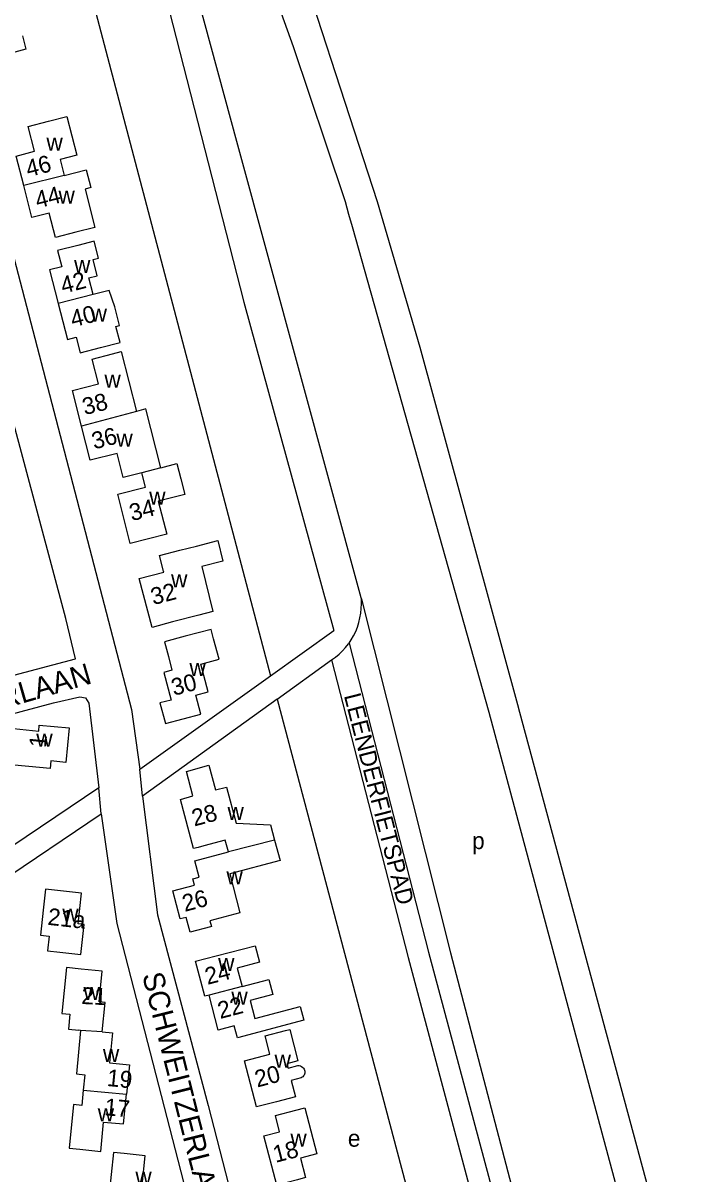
# Model space of a CAD drawing. Extents: x 161093 to 163177, y 379000 to 380904.
# Drawn here: x 162658.3 to 162814.2, y 380357.5 to 380629.6 of the extents above; entities that cross this region are included whole.
import ezdxf

# ---------------------------------------------------------------- set-up
doc = ezdxf.new("R2010")
doc.units = 0
for name, color, linetype in [('BLT_Basislijn', 7, 'Continuous'), ('BLT_Bebouwing', 7, 'Continuous'), ('BLT_Centroide', 7, 'Continuous'), ('BLT_Huisnummer', 7, 'Continuous'), ('BLT_Onderverdeling_panden', 7, 'Continuous'), ('BLT_Straatnaam', 7, 'Continuous'), ('BLT_Straatnaam_verkleind', 7, 'Continuous')]:
    doc.layers.add(name, color=color, linetype=linetype)

msp = doc.modelspace()

# ---------------------------------------------------------------- linework, layer by layer
at = {"layer": 'BLT_Basislijn'}
for p, q in [((162682.53, 380698.36), (162708.97, 380600.8)), ((162726.63, 380634.35), (162741.91, 380587.43)), ((162708.97, 380600.8), (162738.11, 380493.77)), ((162735.18, 380584.45), (162736.02, 380581.49)), ((162710.43, 380563.6), (162731.72, 380485.97)), ((162738.11, 380493.77), (162738.2, 380493.41)), ((162738.2, 380493.41), (162759.26, 380409.76)), ((162716.76, 380475.26), (162731.72, 380485.97)), ((162735.29, 380483.01), (162754.08, 380409.94)), ((162718.35, 380469.79), (162731.15, 380479.02)), ((162731.15, 380479.02), (162749.24, 380408.7)), ((162685.9, 380453.19), (162716.76, 380475.26)), ((162718.35, 380469.79), (162686.52, 380446.86)), ((162768.34, 380466.65), (162806.16, 380325.66)), ((162775.08, 380468.52), (162775.56, 380466.65)), ((162775.56, 380466.65), (162814.19, 380323.58)), ((162686.52, 380446.86), (162685.9, 380453.19)), ((162676.14, 380448.82), (162638.7, 380423.5)), ((162676.76, 380442.66), (162676.14, 380448.82)), ((162647.54, 380422.95), (162676.76, 380442.66)), ((162754.08, 380409.94), (162773.23, 380338.47)), ((162759.26, 380409.76), (162777.73, 380339.31)), ((162749.24, 380408.7), (162768.4, 380337.17))]:
    msp.add_line(p, q, dxfattribs=at)
for points in [[(162521.72, 380713.91), (162569.39, 380726.78), (162570.66, 380726.33), (162600, 380707.66), (162646.36, 380678.17), (162666.62, 380665.58), (162716.76, 380475.26)], [(162674.84, 380697.09), (162690.28, 380642.46), (162710.43, 380563.6)], [(162704.48, 380673.18), (162722.08, 380624.03), (162729.85, 380601.06)], [(162635.73, 380632.52), (162634.81, 380628.02), (162628.89, 380606.34), (162635.55, 380602.41), (162638.7, 380600.16), (162645.01, 380593.94), (162646.61, 380592.03), (162652.23, 380583.53), (162655.59, 380576), (162683.93, 380467.29), (162685.9, 380453.19)], [(162729.85, 380601.06), (162734.4, 380587.43), (162735.18, 380584.45)], [(162741.91, 380587.43), (162752.02, 380552.96), (162775.08, 380468.52)], [(162736.02, 380581.49), (162768.34, 380466.65)], [(162611.52, 380463.97), (162612.48, 380463.94), (162614.96, 380464.57), (162670.7, 380479.32), (162668.42, 380488.85), (162655.43, 380537.18), (162622.45, 380529.94), (162611.45, 380529.55), (162606.04, 380530.03), (162600, 380531.3), (162592.93, 380532.79), (162582.27, 380535.94), (162507.49, 380559.04), (162504.08, 380561.39)], [(162735.29, 380483.01), (162735.81, 380483.78), (162736.37, 380484.75), (162736.86, 380485.76), (162737.28, 380486.79), (162737.62, 380487.86), (162737.88, 380488.95), (162738.07, 380490.05), (162738.18, 380491.16), (162738.2, 380492.28), (162738.2, 380493.41)], [(162731.15, 380479.02), (162732.07, 380479.67), (162732.93, 380480.38), (162733.74, 380481.15), (162734.49, 380481.98), (162735.18, 380482.85), (162735.29, 380483.01)], [(162609.26, 380454.6), (162617.51, 380456.01), (162665.48, 380468.91), (162671.67, 380470.27), (162673.04, 380470.08), (162673.82, 380468.82), (162676.14, 380448.82)], [(162718.35, 380469.79), (162769.85, 380275.36), (162777.91, 380251.24), (162777.23, 380250.72), (162770.85, 380248.18), (162757.24, 380224.32)], [(162686.52, 380446.86), (162690.06, 380418.81), (162702.03, 380373.69), (162725.23, 380283.43), (162725.87, 380280.88), (162726.14, 380277.12), (162726.26, 380268.1), (162725.19, 380258.43), (162721.09, 380245.82), (162714.65, 380234.57), (162708.48, 380227.38), (162705.29, 380224.32)], [(162676.76, 380442.66), (162680.45, 380416.71), (162702.12, 380332.61), (162714.84, 380284.51), (162715.91, 380269.96), (162715.24, 380261.62), (162713.44, 380253.95), (162710.56, 380247.24), (162703.72, 380236.16), (162696.64, 380228.93), (162690.51, 380224.32)]]:
    msp.add_lwpolyline(points, dxfattribs=at)
at = {"layer": 'BLT_Bebouwing'}
msp.add_line((162671.88, 380391.39), (162671.48, 380391.49), dxfattribs=at)
for points in [[(162658.12, 380626.56), (162658.95, 380623.42), (162652.48, 380621.7), (162653.48, 380617.93), (162652.31, 380617.62), (162654.32, 380610.02)], [(162658.42, 380591.15), (162656.63, 380598.16), (162660.96, 380599.27), (162659.46, 380605.17), (162664.28, 380606.4), (162668.62, 380607.5), (162670.95, 380598.38), (162667.02, 380597.37), (162667.98, 380593.59)], [(162667.98, 380593.59), (162673.21, 380594.92), (162674.29, 380590.71), (162672.92, 380590.36), (162675.23, 380581.28), (162670.76, 380580.14), (162665.91, 380578.91), (162664.45, 380584.63), (162660.35, 380583.59), (162658.42, 380591.15)], [(162674.83, 380565.42), (162673.83, 380569.35), (162675.8, 380569.85), (162674.82, 380573.71), (162676.13, 380574.04), (162675.11, 380578.01), (162671.25, 380577.02), (162666.43, 380575.79), (162667.4, 380571.97), (162664.54, 380571.24), (162666.56, 380563.31)], [(162666.56, 380563.31), (162668.74, 380554.79), (162670.83, 380555.32), (162671.77, 380551.63), (162676.61, 380552.87), (162681.21, 380554.04), (162680.23, 380557.88), (162681.07, 380558.09), (162679.95, 380562.49), (162678.64, 380566.39), (162674.83, 380565.42)], [(162672.11, 380534.28), (162669.95, 380542.74), (162676.08, 380544.31), (162674.59, 380550.16), (162679.43, 380551.4), (162681.43, 380551.91), (162685.04, 380537.77)], [(162690.85, 380524.47), (162687.29, 380538.39), (162685.04, 380537.77)], [(162686.31, 380523.27), (162681.95, 380522.15), (162680.5, 380527.85), (162674.16, 380526.23), (162672.11, 380534.28)], [(162690.85, 380524.47), (162694.62, 380525.43), (162695.54, 380521.82), (162696.47, 380518.15), (162693.35, 380517.35), (162690.22, 380516.55), (162692.21, 380508.77), (162683.6, 380506.57), (162680.63, 380518.19), (162687.17, 380519.86), (162686.31, 380523.27)], [(162695.35, 380504.96), (162699.25, 380505.96), (162704.26, 380507.24), (162705.5, 380502.39), (162700.49, 380501.11), (162703.11, 380490.52), (162699.84, 380489.64), (162693.62, 380488), (162688.78, 380486.73), (162685.74, 380498.29), (162691.5, 380499.81), (162691.46, 380500), (162690.51, 380503.73), (162695.35, 380504.96)], [(162701.99, 380471.51), (162700.27, 380478.05), (162704.58, 380479.18), (162703.3, 380484.02), (162702.71, 380486.24), (162696.55, 380484.62), (162691.68, 380483.34), (162692.61, 380479.83), (162693.46, 380476.61), (162691.5, 380476.09), (162693.23, 380469.53), (162690.62, 380468.85), (162691.89, 380464.02), (162700.27, 380466.23), (162699.08, 380470.74), (162701.99, 380471.51)], [(162654.55, 380462.94), (162661.98, 380462.22), (162662.11, 380463.63), (162669.14, 380462.95), (162668.35, 380454.81), (162664.85, 380455.15), (162664.68, 380453.35), (162653.72, 380454.41), (162654.55, 380462.94)], [(162706.79, 380433.67), (162706.06, 380436.44), (162700.96, 380435.07), (162699.66, 380434.72), (162698.58, 380434.43), (162695.46, 380446.07), (162698.42, 380446.87), (162696.86, 380452.69), (162702.18, 380454.12), (162703.74, 380448.3), (162706.32, 380448.99)], [(162706.32, 380448.99), (162708.62, 380440.41), (162716.75, 380440.07), (162717.71, 380436.46)], [(162717.71, 380436.46), (162719, 380431.59), (162707.09, 380428.43)], [(162707.09, 380428.43), (162709.52, 380419.24), (162702.44, 380417.36), (162702.8, 380415.98), (162702.6, 380415.93), (162697.77, 380414.65), (162696.83, 380418.18), (162695.41, 380417.81), (162693.65, 380424.44), (162698.75, 380425.79), (162698.35, 380427.28), (162699.91, 380427.69), (162698.88, 380431.57), (162706.79, 380433.67)], [(162666.99, 380409.97), (162671.96, 380409.42), (162672.73, 380416.46), (162671.26, 380416.62), (162672.07, 380423.93), (162663.6, 380424.87), (162663.05, 380419.87), (162662.4, 380413.99), (162664.43, 380413.76), (162664.05, 380410.29), (162666.99, 380409.97)], [(162702.21, 380399.79), (162701.2, 380399.52), (162699.04, 380407.8), (162703.88, 380409.06), (162713.13, 380411.47), (162714.15, 380407.55), (162708.9, 380406.18), (162710.04, 380401.82)], [(162676.96, 380391.13), (162677.65, 380398.05), (162676.27, 380398.18), (162676.99, 380405.47), (162672.02, 380405.96), (162668.53, 380406.31), (162667.45, 380395.47), (162669.36, 380395.28), (162669.01, 380391.74), (162671.48, 380391.49)], [(162710.04, 380401.82), (162716.35, 380403.47), (162717.27, 380399.91), (162711.92, 380398.52), (162713.03, 380394.26), (162723.75, 380397.09), (162724.61, 380393.86), (162708.92, 380389.69), (162708.18, 380392.54), (162704.35, 380391.54), (162702.21, 380399.79)], [(162671.88, 380391.39), (162670.87, 380381.18), (162672.86, 380380.98), (162672.5, 380377.35)], [(162676.96, 380391.13), (162679.44, 380390.88), (162678.73, 380383.75), (162683.4, 380383.29), (162682.71, 380376.34)], [(162720.28, 380391.41), (162721.28, 380391.67), (162723.21, 380384.25), (162720.62, 380383.58), (162720.89, 380382.56), (162723.18, 380383.16), (162723.54, 380383.14), (162723.84, 380383.04), (162724.09, 380382.93), (162724.36, 380382.71), (162724.55, 380382.49), (162724.68, 380382.27), (162724.76, 380382.03), (162724.83, 380381.82), (162724.84, 380381.6), (162724.81, 380381.34), (162724.77, 380381.14), (162724.67, 380380.88), (162724.55, 380380.7), (162724.39, 380380.5), (162724.25, 380380.37), (162724.02, 380380.23), (162721.65, 380379.61), (162722.66, 380375.76), (162718.19, 380374.6), (162713.4, 380373.35), (162710.56, 380384.26), (162716.57, 380385.82), (162715.44, 380390.15), (162720.28, 380391.41)], [(162672.5, 380377.35), (162672.14, 380373.71), (162670.16, 380373.91), (162669.14, 380363.59), (162671.65, 380363.34), (162676.62, 380362.84), (162677.31, 380369.79), (162682.01, 380369.33), (162682.71, 380376.34)], [(162723.11, 380356.16), (162718.2, 380354.88), (162715.17, 380366.5), (162718.89, 380367.47), (162717.88, 380371.36), (162722.72, 380372.62), (162724.85, 380373.17), (162727.69, 380362.27), (162723.81, 380361.26), (162725.01, 380356.66), (162723.11, 380356.16)], [(162690.33, 380347.37), (162691.07, 380354.37), (162686.41, 380354.86), (162687.15, 380361.81), (162682.18, 380362.33), (162679.66, 380362.6), (162678.56, 380352.21), (162680.52, 380352), (162680.14, 380348.45)]]:
    msp.add_lwpolyline(points, dxfattribs=at)
at = {"layer": 'BLT_Onderverdeling_panden'}
for p, q in [((162667.98, 380593.59), (162658.42, 380591.15)), ((162674.83, 380565.42), (162666.56, 380563.31)), ((162685.04, 380537.77), (162672.11, 380534.28)), ((162690.85, 380524.47), (162686.31, 380523.27)), ((162717.71, 380436.46), (162706.79, 380433.67)), ((162710.04, 380401.82), (162702.21, 380399.79)), ((162676.96, 380391.13), (162671.88, 380391.39)), ((162672.5, 380377.35), (162682.71, 380376.34))]:
    msp.add_line(p, q, dxfattribs=at)

# ---------------------------------------------------------------- texts
at = {"layer": 'BLT_Centroide'}
for s, p in [('w', (162663.8, 380599.41)), ('w', (162666.65, 380586.91)), ('w', (162670.33, 380570.53)), ('w', (162674.24, 380559)), ('w', (162677.5, 380543.38)), ('w', (162680.33, 380529.44)), ('w', (162688.08, 380515.73)), ('w', (162693.25, 380496.17)), ('w', (162697.59, 380475.22)), ('w', (162661.41, 380458.5)), ('w', (162706.58, 380441.22)), ('p', (162764.36, 380434.3)), ('w', (162706.33, 380425.98)), ('w', (162667.56, 380417.17)), ('w', (162704.36, 380405.5)), ('w', (162672.55, 380398.62)), ('w', (162707.49, 380397.5)), ('w', (162677.14, 380383.98)), ('w', (162717.7, 380382.61)), ('w', (162675.92, 380369.95)), ('w', (162721.44, 380364)), ('e', (162735.01, 380363.95)), ('w', (162684.81, 380355.02))]:
    msp.add_text(s, height=4, dxfattribs=at).set_placement(p)
at = {"layer": 'BLT_Huisnummer'}
for s, rotation, p in [('46', 14.3151, (162659.5, 380593.14)), ('44', 14.3114, (162661.7, 380585.75)), ('42', 14.3132, (162667.72, 380565.57)), ('40', 14.3114, (162670.04, 380557.63)), ('38', 14.3202, (162672.85, 380536.88)), ('36', 14.3206, (162675.07, 380528.78)), ('34', 14.3037, (162683.96, 380511.82)), ('32', 14.7587, (162689.05, 380491.97)), ('30', 14.7712, (162693.89, 380470.53)), ('1', 84.4734, (162663.65, 380458.18)), ('28', 15.027, (162698.74, 380439.65)), ('26', 14.82, (162696.48, 380419.46)), ('21a', 353.7156, (162663.94, 380416.43)), ('24', 14.5738, (162701.84, 380402.21)), ('21', 357.0392, (162671.98, 380397.71)), ('22', 14.6059, (162704.85, 380394.14)), ('19', 354.3472, (162677.96, 380378.33)), ('20', 14.5838, (162713.6, 380377.94)), ('17', 354.3407, (162677.36, 380371.45)), ('18', 14.5871, (162717.92, 380360.13))]:
    msp.add_text(s, height=4, rotation=rotation, dxfattribs=at).set_placement(p)
at = {"layer": 'BLT_Straatnaam'}
for s, rotation, p in [('JENNERLAAN', 16.1277, (162632.34, 380461.27)), ('SCHWEITZERLAAN', 284.1212, (162686.39, 380404.54))]:
    msp.add_text(s, height=5, rotation=rotation, dxfattribs=at).set_placement(p)
at = {"layer": 'BLT_Straatnaam_verkleind'}
msp.add_text('LEENDERFIETSPAD', height=4, rotation=284.4211, dxfattribs=at).set_placement((162734.06, 380470.6))

doc.saveas('drawing.dxf')
